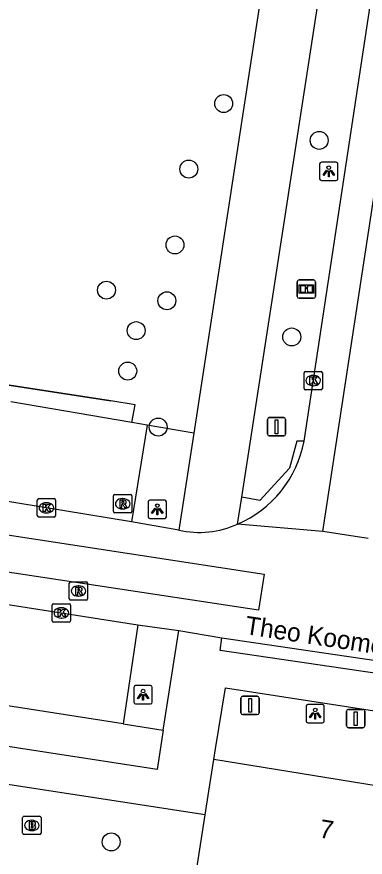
# Model space of a CAD drawing. Extents: x 161094 to 161705, y 379509 to 380907.
# Drawn here: x 161323.3 to 161342.3, y 380460.02 to 380505.83 of the extents above; entities that cross this region are included whole.
import ezdxf

# ---------------------------------------------------------------- set-up
doc = ezdxf.new("R2010")
doc.units = 0
for name, color, linetype in [('IMGEO_Afsluitpaal', 7, 'Continuous'), ('IMGEO_Boom', 7, 'Continuous'), ('IMGEO_Brandkraan', 7, 'Continuous'), ('IMGEO_Fietspad_gesloten', 7, 'Continuous'), ('IMGEO_Groenvoorziening', 7, 'Continuous'), ('IMGEO_Hek', 7, 'Continuous'), ('IMGEO_Informatiebord', 7, 'Continuous'), ('IMGEO_Kolk', 7, 'Continuous'), ('IMGEO_Lichtpunt', 7, 'Continuous'), ('IMGEO_Openbare_ruimte_label', 7, 'Continuous'), ('IMGEO_Pand', 7, 'Continuous'), ('IMGEO_Pand_nummerreeks', 7, 'Continuous'), ('IMGEO_Parkeervlak_open', 7, 'Continuous'), ('IMGEO_Rijbaan_lokaal_gesloten', 7, 'Continuous'), ('IMGEO_Rijbaan_lokaal_halfverhard', 7, 'Continuous'), ('IMGEO_Rijbaan_lokaal_open', 7, 'Continuous'), ('IMGEO_Rioolput', 7, 'Continuous'), ('IMGEO_Verkeersbordpaal', 7, 'Continuous'), ('IMGEO_Voetpad_gesloten', 7, 'Continuous')]:
    doc.layers.add(name, color=color, linetype=linetype)

msp = doc.modelspace()

# ---------------------------------------------------------------- linework, layer by layer
at = {"layer": 'IMGEO_Afsluitpaal'}
for p, q in [((161335.527, 380467.894), (161335.527, 380468.694)), ((161335.527, 380468.694), (161335.527, 380467.894)), ((161335.627, 380468.794), (161336.417, 380468.794)), ((161336.417, 380468.794), (161335.627, 380468.794)), ((161336.517, 380468.694), (161336.517, 380467.894)), ((161336.517, 380467.894), (161336.517, 380468.694)), ((161341.391, 380468.077), (161342.181, 380468.077)), ((161342.181, 380468.077), (161341.391, 380468.077)), ((161336.417, 380467.794), (161335.627, 380467.794)), ((161335.627, 380467.794), (161336.417, 380467.794)), ((161341.291, 380467.177), (161341.291, 380467.977)), ((161341.291, 380467.977), (161341.291, 380467.177)), ((161342.281, 380467.977), (161342.281, 380467.177)), ((161342.281, 380467.177), (161342.281, 380467.977)), ((161342.181, 380467.077), (161341.391, 380467.077)), ((161341.391, 380467.077), (161342.181, 380467.077))]:
    msp.add_line(p, q, dxfattribs=at)
for points in [[(161335.947, 380468.669), (161336.097, 380468.669), (161336.097, 380467.919), (161335.947, 380467.919), (161335.947, 380468.669)], [(161341.711, 380467.952), (161341.861, 380467.952), (161341.861, 380467.202), (161341.711, 380467.202), (161341.711, 380467.952)]]:
    msp.add_lwpolyline(points, dxfattribs=at)
for centre, start, end in [((161335.627, 380468.694), 90, 180), ((161335.627, 380468.694), 90, 180), ((161336.417, 380468.694), 0, 90), ((161336.417, 380468.694), 360, 90), ((161341.391, 380467.977), 90, 180), ((161341.391, 380467.977), 90, 180), ((161342.181, 380467.977), 0, 90), ((161342.181, 380467.977), 360, 90), ((161335.627, 380467.894), 180, 270), ((161335.627, 380467.894), 180, 270), ((161336.417, 380467.894), 270, 0), ((161336.417, 380467.894), 270, 0), ((161341.391, 380467.177), 180, 270), ((161341.391, 380467.177), 180, 270), ((161342.181, 380467.177), 270, 0), ((161342.181, 380467.177), 270, 0)]:
    msp.add_arc(centre, 0.1, start, end, dxfattribs=at)
at = {"layer": 'IMGEO_Boom'}
for centre in [(161334.583, 380501.099), (161339.794, 380499.091), (161332.68, 380497.526), (161331.926, 380493.393), (161328.188, 380490.93), (161331.484, 380490.349), (161329.809, 380488.723), (161338.297, 380488.378), (161329.349, 380486.517), (161331.012, 380483.465), (161328.447, 380460.856)]:
    msp.add_circle(centre, 0.489, dxfattribs=at)
at = {"layer": 'IMGEO_Brandkraan'}
for p, q in [((161323.617, 380461.327), (161323.617, 380462.179)), ((161323.692, 380462.253), (161324.544, 380462.253)), ((161324.618, 380462.179), (161324.618, 380461.327)), ((161324.105, 380462.033), (161324.13, 380462.033)), ((161324.544, 380461.253), (161323.692, 380461.253)), ((161324.128, 380461.473), (161324.103, 380461.473))]:
    msp.add_line(p, q, dxfattribs=at)
for points in [[(161323.617, 380461.327), (161323.617, 380462.179)], [(161323.692, 380462.253), (161324.544, 380462.253)], [(161324.618, 380462.179), (161324.618, 380461.327)], [(161323.965, 380461.953), (161323.965, 380461.553), (161324.178, 380461.553)], [(161324.196, 380461.953), (161323.965, 380461.953)], [(161324.144, 380461.872), (161324.09, 380461.872), (161324.09, 380461.796)], [(161324.09, 380461.796), (161324.143, 380461.796)], [(161324.152, 380461.72), (161324.09, 380461.72), (161324.09, 380461.639)], [(161324.544, 380461.253), (161323.692, 380461.253)], [(161324.09, 380461.639), (161324.152, 380461.639)]]:
    msp.add_lwpolyline(points, dxfattribs=at)
for centre, radius, start, end in [((161323.694, 380462.177), 0.0765, 91.552, 178.448), ((161323.694, 380462.177), 0.0765, 91.552, 178.448), ((161324.542, 380462.177), 0.0765, 1.552, 88.448), ((161324.542, 380462.177), 0.0765, 1.552, 88.448), ((161324.145, 380461.834), 0.0379, 267.8285, 90.9355), ((161324.153, 380461.679), 0.0404, 269.8759, 90.5077), ((161324.2, 380461.808), 0.145, 59.4692, 91.5367), ((161324.225, 380461.855), 0.0922, 285.5137, 58.1501), ((161324.23, 380461.663), 0.105, 301.3115, 78.989), ((161323.694, 380461.329), 0.0765, 181.552, 268.448), ((161323.694, 380461.329), 0.0765, 181.552, 268.448), ((161324.184, 380461.804), 0.251, 268.6676, 293.5347), ((161324.542, 380461.329), 0.0765, 271.552, 358.448), ((161324.542, 380461.329), 0.0765, 271.552, 358.448)]:
    msp.add_arc(centre, radius, start, end, dxfattribs=at)
for centre, major_axis, ratio, start_param, end_param in [((161324.104, 380461.753), (-0.387, 0.002), 0.722429, 4.712389, 7.853982), ((161324.129, 380461.753), (-0.39, 0.002), 0.717154, 1.570796, 4.712389)]:
    msp.add_ellipse(centre, major_axis=major_axis, ratio=ratio, start_param=start_param, end_param=end_param, dxfattribs=at)
at = {"layer": 'IMGEO_Fietspad_gesloten'}
for points in [[(161335.568, 380479.642), (161342.437, 380524.075)], [(161336.97, 380509.331), (161332.95, 380483.131)], [(161332.95, 380483.131), (161332.14, 380477.853)]]:
    msp.add_lwpolyline(points, dxfattribs=at)
at = {"layer": 'IMGEO_Groenvoorziening'}
for points in [[(161329.567, 380483.714), (161329.746, 380484.686), (161328.428, 380484.889), (161302.904, 380488.816)], [(161332.95, 380483.131), (161330.403, 380483.57)], [(161329.093, 380467.287), (161331.289, 380466.946)]]:
    msp.add_lwpolyline(points, dxfattribs=at)
at = {"layer": 'IMGEO_Hek'}
msp.add_lwpolyline([(161302.904, 380488.816), (161328.428, 380484.889)], dxfattribs=at)
at = {"layer": 'IMGEO_Informatiebord'}
for p, q in [((161338.7, 380491.488), (161339.49, 380491.488)), ((161339.49, 380491.488), (161338.7, 380491.488)), ((161338.6, 380490.588), (161338.6, 380491.388)), ((161338.6, 380491.388), (161338.6, 380490.588)), ((161339.59, 380491.388), (161339.59, 380490.588)), ((161339.59, 380490.588), (161339.59, 380491.388)), ((161339.49, 380490.488), (161338.7, 380490.488)), ((161338.7, 380490.488), (161339.49, 380490.488))]:
    msp.add_line(p, q, dxfattribs=at)
for points in [[(161338.701, 380491.22), (161339.489, 380491.22), (161339.489, 380490.756), (161338.701, 380490.756), (161338.701, 380491.22)], [(161338.766, 380491.155), (161338.766, 380490.821), (161339.041, 380490.821), (161339.042, 380491.034), (161339.146, 380491.035), (161339.147, 380490.821), (161339.424, 380490.821), (161339.424, 380491.155), (161339.148, 380491.155), (161339.148, 380491.075), (161339.042, 380491.075), (161339.042, 380491.155), (161338.766, 380491.155)]]:
    msp.add_lwpolyline(points, dxfattribs=at)
for centre, start, end in [((161338.7, 380491.388), 90, 180), ((161338.7, 380491.388), 90, 180), ((161339.49, 380491.388), 0, 90), ((161339.49, 380491.388), 360, 90), ((161338.7, 380490.588), 180, 270), ((161338.7, 380490.588), 180, 270), ((161339.49, 380490.588), 270, 0), ((161339.49, 380490.588), 270, 0)]:
    msp.add_arc(centre, 0.1, start, end, dxfattribs=at)
at = {"layer": 'IMGEO_Kolk'}
for p, q in [((161338.967, 380485.575), (161338.967, 380486.427)), ((161339.042, 380486.501), (161339.894, 380486.501)), ((161339.968, 380486.427), (161339.968, 380485.575)), ((161339.455, 380486.281), (161339.48, 380486.281)), ((161339.894, 380485.501), (161339.042, 380485.501)), ((161339.478, 380485.721), (161339.453, 380485.721)), ((161324.488, 380479.564), (161325.34, 380479.564)), ((161324.413, 380478.638), (161324.413, 380479.49)), ((161324.901, 380479.344), (161324.926, 380479.344)), ((161325.414, 380479.49), (161325.414, 380478.638)), ((161324.924, 380478.784), (161324.899, 380478.784)), ((161325.34, 380478.564), (161324.488, 380478.564)), ((161325.228, 380472.913), (161325.228, 380473.765)), ((161325.303, 380473.839), (161326.155, 380473.839)), ((161325.716, 380473.619), (161325.741, 380473.619)), ((161326.229, 380473.765), (161326.229, 380472.913)), ((161326.155, 380472.839), (161325.303, 380472.839)), ((161325.739, 380473.059), (161325.714, 380473.059))]:
    msp.add_line(p, q, dxfattribs=at)
for points in [[(161338.967, 380485.575), (161338.967, 380486.427)], [(161339.042, 380486.501), (161339.894, 380486.501)], [(161339.968, 380486.427), (161339.968, 380485.575)], [(161339.288, 380486.201), (161339.411, 380486.201), (161339.411, 380486.05), (161339.541, 380486.201), (161339.705, 380486.201), (161339.559, 380486.05), (161339.712, 380485.801), (161339.56, 380485.801), (161339.475, 380485.965), (161339.411, 380485.898), (161339.411, 380485.801), (161339.288, 380485.801), (161339.288, 380486.201)], [(161339.894, 380485.501), (161339.042, 380485.501)], [(161324.488, 380479.564), (161325.34, 380479.564)], [(161324.413, 380478.638), (161324.413, 380479.49)], [(161324.734, 380479.264), (161324.857, 380479.264), (161324.857, 380479.113), (161324.987, 380479.264), (161325.151, 380479.264), (161325.005, 380479.113), (161325.158, 380478.864), (161325.006, 380478.864), (161324.921, 380479.028), (161324.857, 380478.961), (161324.857, 380478.864), (161324.734, 380478.864), (161324.734, 380479.264)], [(161325.414, 380479.49), (161325.414, 380478.638)], [(161325.34, 380478.564), (161324.488, 380478.564)], [(161325.228, 380472.913), (161325.228, 380473.765)], [(161325.303, 380473.839), (161326.155, 380473.839)], [(161326.229, 380473.765), (161326.229, 380472.913)], [(161325.549, 380473.539), (161325.672, 380473.539), (161325.672, 380473.388), (161325.802, 380473.539), (161325.966, 380473.539), (161325.82, 380473.388), (161325.973, 380473.139), (161325.821, 380473.139), (161325.736, 380473.303), (161325.672, 380473.236), (161325.672, 380473.139), (161325.549, 380473.139), (161325.549, 380473.539)], [(161326.155, 380472.839), (161325.303, 380472.839)]]:
    msp.add_lwpolyline(points, dxfattribs=at)
for centre, start, end in [((161339.044, 380486.425), 91.552, 178.448), ((161339.044, 380486.425), 91.552, 178.448), ((161339.892, 380486.425), 1.552, 88.448), ((161339.892, 380486.425), 1.552, 88.448), ((161339.044, 380485.577), 181.552, 268.448), ((161339.044, 380485.577), 181.552, 268.448), ((161339.892, 380485.577), 271.552, 358.448), ((161339.892, 380485.577), 271.552, 358.448), ((161324.49, 380479.488), 91.552, 178.448), ((161324.49, 380479.488), 91.552, 178.448), ((161325.338, 380479.488), 1.552, 88.448), ((161325.338, 380479.488), 1.552, 88.448), ((161324.49, 380478.64), 181.552, 268.448), ((161324.49, 380478.64), 181.552, 268.448), ((161325.338, 380478.64), 271.552, 358.448), ((161325.338, 380478.64), 271.552, 358.448), ((161325.305, 380473.763), 91.552, 178.448), ((161325.305, 380473.763), 91.552, 178.448), ((161326.153, 380473.763), 1.552, 88.448), ((161326.153, 380473.763), 1.552, 88.448), ((161325.305, 380472.915), 181.552, 268.448), ((161325.305, 380472.915), 181.552, 268.448), ((161326.153, 380472.915), 271.552, 358.448), ((161326.153, 380472.915), 271.552, 358.448)]:
    msp.add_arc(centre, 0.0765, start, end, dxfattribs=at)
for centre, major_axis, ratio, start_param, end_param in [((161339.454, 380486.001), (-0.387, 0.002), 0.722429, 4.712389, 7.853982), ((161339.479, 380486.001), (-0.39, 0.002), 0.717154, 1.570796, 4.712389), ((161324.9, 380479.064), (-0.387, 0.002), 0.722429, 4.712389, 7.853982), ((161324.925, 380479.064), (-0.39, 0.002), 0.717154, 1.570796, 4.712389), ((161325.715, 380473.339), (-0.387, 0.002), 0.722429, 4.712389, 7.853982), ((161325.74, 380473.339), (-0.39, 0.002), 0.717154, 1.570796, 4.712389)]:
    msp.add_ellipse(centre, major_axis=major_axis, ratio=ratio, start_param=start_param, end_param=end_param, dxfattribs=at)
at = {"layer": 'IMGEO_Lichtpunt'}
for p, q in [((161340.721, 380497.902), (161339.913, 380497.902)), ((161340.721, 380497.902), (161339.913, 380497.902)), ((161339.819, 380497.807), (161339.819, 380497)), ((161339.819, 380497.807), (161339.819, 380497)), ((161340.815, 380497), (161340.815, 380497.807)), ((161340.815, 380497), (161340.815, 380497.807)), ((161339.913, 380496.906), (161340.721, 380496.906)), ((161339.913, 380496.906), (161340.721, 380496.906)), ((161330.463, 380479.385), (161330.463, 380478.578)), ((161330.463, 380479.385), (161330.463, 380478.578)), ((161331.365, 380479.48), (161330.557, 380479.48)), ((161331.365, 380479.48), (161330.557, 380479.48)), ((161331.459, 380478.578), (161331.459, 380479.385)), ((161331.459, 380478.578), (161331.459, 380479.385)), ((161330.557, 380478.484), (161331.365, 380478.484)), ((161330.557, 380478.484), (161331.365, 380478.484)), ((161329.686, 380469.28), (161329.686, 380468.473)), ((161329.686, 380469.28), (161329.686, 380468.473)), ((161330.588, 380469.375), (161329.78, 380469.375)), ((161330.588, 380469.375), (161329.78, 380469.375)), ((161330.682, 380468.473), (161330.682, 380469.28)), ((161330.682, 380468.473), (161330.682, 380469.28)), ((161329.78, 380468.379), (161330.588, 380468.379)), ((161329.78, 380468.379), (161330.588, 380468.379)), ((161339.076, 380468.248), (161339.076, 380467.441)), ((161339.076, 380468.248), (161339.076, 380467.441)), ((161339.978, 380468.343), (161339.17, 380468.343)), ((161339.978, 380468.343), (161339.17, 380468.343)), ((161340.072, 380467.441), (161340.072, 380468.248)), ((161340.072, 380467.441), (161340.072, 380468.248)), ((161339.17, 380467.347), (161339.978, 380467.347)), ((161339.17, 380467.347), (161339.978, 380467.347))]:
    msp.add_line(p, q, dxfattribs=at)
for points in [[(161340.193, 380497.471), (161340.232, 380497.443), (161340.044, 380497.181), (161340.006, 380497.208), (161340.193, 380497.471)], [(161340.295, 380497.423), (161340.342, 380497.423), (161340.342, 380497.101), (161340.295, 380497.101), (161340.295, 380497.423)], [(161340.405, 380497.443), (161340.443, 380497.47), (161340.63, 380497.208), (161340.591, 380497.18), (161340.405, 380497.443)], [(161330.837, 380479.049), (161330.876, 380479.021), (161330.688, 380478.759), (161330.65, 380478.786), (161330.837, 380479.049)], [(161331.049, 380479.021), (161331.087, 380479.048), (161331.274, 380478.786), (161331.235, 380478.758), (161331.049, 380479.021)], [(161330.939, 380479.001), (161330.986, 380479.001), (161330.986, 380478.679), (161330.939, 380478.679), (161330.939, 380479.001)], [(161330.06, 380468.944), (161330.099, 380468.916), (161329.911, 380468.654), (161329.873, 380468.681), (161330.06, 380468.944)], [(161330.162, 380468.896), (161330.209, 380468.896), (161330.209, 380468.574), (161330.162, 380468.574), (161330.162, 380468.896)], [(161330.272, 380468.916), (161330.31, 380468.943), (161330.497, 380468.681), (161330.458, 380468.653), (161330.272, 380468.916)], [(161339.45, 380467.912), (161339.489, 380467.884), (161339.301, 380467.622), (161339.263, 380467.649), (161339.45, 380467.912)], [(161339.552, 380467.864), (161339.599, 380467.864), (161339.599, 380467.542), (161339.552, 380467.542), (161339.552, 380467.864)], [(161339.662, 380467.884), (161339.7, 380467.911), (161339.887, 380467.649), (161339.848, 380467.621), (161339.662, 380467.884)]]:
    msp.add_lwpolyline(points, dxfattribs=at)
for centre in [(161340.318, 380497.605), (161330.962, 380479.183), (161330.185, 380469.078), (161339.575, 380468.046)]:
    msp.add_circle(centre, 0.0994, dxfattribs=at)
for centre, start, end in [((161339.913, 380497.807), 90, 180), ((161339.913, 380497.807), 90, 180), ((161340.721, 380497.807), 0, 90), ((161340.721, 380497.807), 0, 90), ((161339.913, 380497), 180, 270), ((161339.913, 380497), 180, 270), ((161340.721, 380497), 270, 0), ((161340.721, 380497), 270, 360), ((161330.557, 380479.385), 90, 180), ((161330.557, 380479.385), 90, 180), ((161331.365, 380479.385), 0, 90), ((161331.365, 380479.385), 0, 90), ((161330.557, 380478.578), 180, 270), ((161330.557, 380478.578), 180, 270), ((161331.365, 380478.578), 270, 0), ((161331.365, 380478.578), 270, 360), ((161329.78, 380469.28), 90, 180), ((161329.78, 380469.28), 90, 180), ((161330.588, 380469.28), 0, 90), ((161330.588, 380469.28), 0, 90), ((161329.78, 380468.473), 180, 270), ((161329.78, 380468.473), 180, 270), ((161330.588, 380468.473), 270, 0), ((161330.588, 380468.473), 270, 360), ((161339.17, 380468.248), 90, 180), ((161339.17, 380468.248), 90, 180), ((161339.978, 380468.248), 0, 90), ((161339.978, 380468.248), 0, 90), ((161339.17, 380467.441), 180, 270), ((161339.17, 380467.441), 180, 270), ((161339.978, 380467.441), 270, 0), ((161339.978, 380467.441), 270, 360)]:
    msp.add_arc(centre, 0.0946, start, end, dxfattribs=at)
at = {"layer": 'IMGEO_Pand'}
for points in [[(161333.579, 380462.328), (161333.782, 380463.629), (161334.051, 380465.355)], [(161347.044, 380463.247), (161334.728, 380465.245), (161334.051, 380465.355)], [(161349.861, 380451.744), (161348.112, 380452.012), (161348.085, 380451.838), (161347.76, 380451.888), (161347.883, 380452.692), (161332.452, 380455.091), (161333.579, 380462.328)]]:
    msp.add_lwpolyline(points, dxfattribs=at)
at = {"layer": 'IMGEO_Parkeervlak_open'}
for points in [[(161329.567, 380483.714), (161322.976, 380484.849)], [(161330.403, 380483.57), (161329.567, 380483.714)], [(161330.403, 380483.57), (161329.555, 380478.303)], [(161329.904, 380472.69), (161329.093, 380467.287)], [(161329.093, 380467.287), (161319.647, 380468.755)]]:
    msp.add_lwpolyline(points, dxfattribs=at)
at = {"layer": 'IMGEO_Rijbaan_lokaal_gesloten'}
for points in [[(161339.984, 380477.773), (161375.194, 380708.235), (161388.922, 380797.51), (161396.234, 380843.996), (161396.663, 380846.991)], [(161338.966, 380482.69), (161344.46, 380518.897)], [(161336.484, 380473.48), (161285.911, 380481.132), (161278.697, 380482.355), (161219.62, 380491.428), (161219.91, 380493.339), (161336.783, 380475.457), (161336.484, 380473.48)], [(161329.555, 380478.303), (161322.111, 380479.523)], [(161332.14, 380477.853), (161329.555, 380478.303)], [(161339.984, 380477.773), (161335.342, 380478.178)], [(161342.463, 380477.394), (161339.984, 380477.773)], [(161320.483, 380474.154), (161329.904, 380472.69)], [(161329.904, 380472.69), (161332.128, 380472.377)], [(161332.128, 380472.377), (161334.483, 380471.977)], [(161334.483, 380471.977), (161352.537, 380469.322)]]:
    msp.add_lwpolyline(points, dxfattribs=at)
for centre, radius, start, end in [((161332.948, 380483.812), 6.122, 293.0226, 349.4352), ((161333.259, 380482.766), 5.039, 257.1704, 294.4209)]:
    msp.add_arc(centre, radius, start, end, dxfattribs=at)
at = {"layer": 'IMGEO_Rijbaan_lokaal_halfverhard'}
msp.add_lwpolyline([(161352.358, 380468.658), (161334.385, 380471.286), (161334.483, 380471.977)], dxfattribs=at)
at = {"layer": 'IMGEO_Rijbaan_lokaal_open'}
for points in [[(161338.966, 380482.69), (161338.571, 380482.699), (161338.173, 380481.229), (161336.557, 380479.455), (161335.568, 380479.642)], [(161335.342, 380478.178), (161335.568, 380479.642)]]:
    msp.add_lwpolyline(points, dxfattribs=at)
at = {"layer": 'IMGEO_Rioolput'}
for p, q in [((161328.575, 380478.86), (161328.575, 380479.712)), ((161328.65, 380479.786), (161329.502, 380479.786)), ((161329.063, 380479.566), (161329.088, 380479.566)), ((161329.576, 380479.712), (161329.576, 380478.86)), ((161329.502, 380478.786), (161328.65, 380478.786)), ((161329.086, 380479.006), (161329.061, 380479.006)), ((161326.161, 380474.104), (161326.161, 380474.956)), ((161326.236, 380475.03), (161327.088, 380475.03)), ((161327.162, 380474.956), (161327.162, 380474.104)), ((161326.649, 380474.81), (161326.674, 380474.81)), ((161327.088, 380474.03), (161326.236, 380474.03)), ((161326.672, 380474.25), (161326.647, 380474.25))]:
    msp.add_line(p, q, dxfattribs=at)
for points in [[(161328.575, 380478.86), (161328.575, 380479.712)], [(161328.65, 380479.786), (161329.502, 380479.786)], [(161329.576, 380479.712), (161329.576, 380478.86)], [(161329.164, 380479.484), (161328.912, 380479.486), (161328.912, 380479.086)], [(161328.912, 380479.086), (161329.036, 380479.086), (161329.036, 380479.248), (161329.047, 380479.248)], [(161329.09, 380479.405), (161329.036, 380479.405), (161329.036, 380479.324)], [(161329.036, 380479.324), (161329.088, 380479.324)], [(161329.094, 380479.219), (161329.165, 380479.086), (161329.305, 380479.086), (161329.24, 380479.212)], [(161329.502, 380478.786), (161328.65, 380478.786)], [(161326.161, 380474.104), (161326.161, 380474.956)], [(161326.236, 380475.03), (161327.088, 380475.03)], [(161327.162, 380474.956), (161327.162, 380474.104)], [(161326.75, 380474.728), (161326.498, 380474.73), (161326.498, 380474.33)], [(161326.498, 380474.33), (161326.622, 380474.33), (161326.622, 380474.492), (161326.633, 380474.492)], [(161326.676, 380474.649), (161326.622, 380474.649), (161326.622, 380474.568)], [(161326.622, 380474.568), (161326.674, 380474.568)], [(161327.088, 380474.03), (161326.236, 380474.03)], [(161326.68, 380474.463), (161326.751, 380474.33), (161326.891, 380474.33), (161326.826, 380474.456)]]:
    msp.add_lwpolyline(points, dxfattribs=at)
for centre, radius, start, end in [((161328.652, 380479.71), 0.0765, 91.552, 178.448), ((161328.652, 380479.71), 0.0765, 91.552, 178.448), ((161329.5, 380479.71), 0.0765, 1.552, 88.448), ((161329.5, 380479.71), 0.0765, 1.552, 88.448), ((161329.046, 380479.195), 0.0533, 26.0293, 88.6989), ((161329.072, 380479.513), 0.19, 274.7715, 282.9687), ((161329.096, 380479.309), 0.0964, 77.0061, 93.1865), ((161329.11, 380479.366), 0.0378, 276.6634, 79.6772), ((161329.163, 380479.374), 0.109, 350.3612, 89.416), ((161329.161, 380479.374), 0.112, 277.5842, 350.9817), ((161329.145, 380479.159), 0.108, 29.5134, 73.7905), ((161328.652, 380478.862), 0.0765, 181.552, 268.448), ((161328.652, 380478.862), 0.0765, 181.552, 268.448), ((161329.5, 380478.862), 0.0765, 271.552, 358.448), ((161329.5, 380478.862), 0.0765, 271.552, 358.448), ((161326.238, 380474.954), 0.0765, 91.552, 178.448), ((161326.238, 380474.954), 0.0765, 91.552, 178.448), ((161327.086, 380474.954), 0.0765, 1.552, 88.448), ((161327.086, 380474.954), 0.0765, 1.552, 88.448), ((161326.632, 380474.439), 0.0533, 26.0293, 88.6989), ((161326.658, 380474.757), 0.19, 274.7715, 282.9687), ((161326.682, 380474.553), 0.0964, 77.0061, 93.1865), ((161326.696, 380474.61), 0.0378, 276.6634, 79.6772), ((161326.749, 380474.618), 0.109, 350.3612, 89.416), ((161326.747, 380474.618), 0.112, 277.5842, 350.9817), ((161326.731, 380474.403), 0.108, 29.5134, 73.7905), ((161326.238, 380474.106), 0.0765, 181.552, 268.448), ((161326.238, 380474.106), 0.0765, 181.552, 268.448), ((161327.086, 380474.106), 0.0765, 271.552, 358.448), ((161327.086, 380474.106), 0.0765, 271.552, 358.448)]:
    msp.add_arc(centre, radius, start, end, dxfattribs=at)
for centre, major_axis, ratio, start_param, end_param in [((161329.062, 380479.286), (-0.387, 0.002), 0.722429, 4.712389, 7.853982), ((161329.087, 380479.286), (-0.39, 0.002), 0.717154, 1.570796, 4.712389), ((161326.648, 380474.53), (-0.387, 0.002), 0.722429, 4.712389, 7.853982), ((161326.673, 380474.53), (-0.39, 0.002), 0.717154, 1.570796, 4.712389)]:
    msp.add_ellipse(centre, major_axis=major_axis, ratio=ratio, start_param=start_param, end_param=end_param, dxfattribs=at)
at = {"layer": 'IMGEO_Verkeersbordpaal'}
for p, q in [((161336.972, 380483.08), (161336.972, 380483.88)), ((161336.972, 380483.88), (161336.972, 380483.08)), ((161337.072, 380483.98), (161337.862, 380483.98)), ((161337.862, 380483.98), (161337.072, 380483.98)), ((161337.962, 380483.88), (161337.962, 380483.08)), ((161337.962, 380483.08), (161337.962, 380483.88)), ((161337.862, 380482.98), (161337.072, 380482.98)), ((161337.072, 380482.98), (161337.862, 380482.98))]:
    msp.add_line(p, q, dxfattribs=at)
msp.add_lwpolyline([(161337.392, 380483.855), (161337.542, 380483.855), (161337.542, 380483.105), (161337.392, 380483.105), (161337.392, 380483.855)], dxfattribs=at)
for centre, start, end in [((161337.072, 380483.88), 90, 180), ((161337.072, 380483.88), 90, 180), ((161337.862, 380483.88), 0, 90), ((161337.862, 380483.88), 360, 90), ((161337.072, 380483.08), 180, 270), ((161337.072, 380483.08), 180, 270), ((161337.862, 380483.08), 270, 0), ((161337.862, 380483.08), 270, 0)]:
    msp.add_arc(centre, 0.1, start, end, dxfattribs=at)
at = {"layer": 'IMGEO_Voetpad_gesloten'}
for points in [[(161331.289, 380466.946), (161332.128, 380472.377)], [(161331.289, 380466.946), (161330.957, 380464.795), (161300.239, 380469.535), (161300.574, 380471.68)], [(161334.051, 380465.355), (161334.13, 380465.931), (161334.684, 380469.253), (161347.648, 380467.248)], [(161333.579, 380462.328), (161304.447, 380466.803)]]:
    msp.add_lwpolyline(points, dxfattribs=at)

# ---------------------------------------------------------------- texts
at = {"layer": 'IMGEO_Openbare_ruimte_label'}
msp.add_text('Theo Koomenlaan', height=1, rotation=351.3758, dxfattribs=at).set_placement((161335.704, 380472.189))
at = {"layer": 'IMGEO_Pand_nummerreeks'}
msp.add_text('7', height=1, rotation=350.7868, dxfattribs=at).set_placement((161339.751, 380461.108))

doc.saveas('drawing.dxf')
